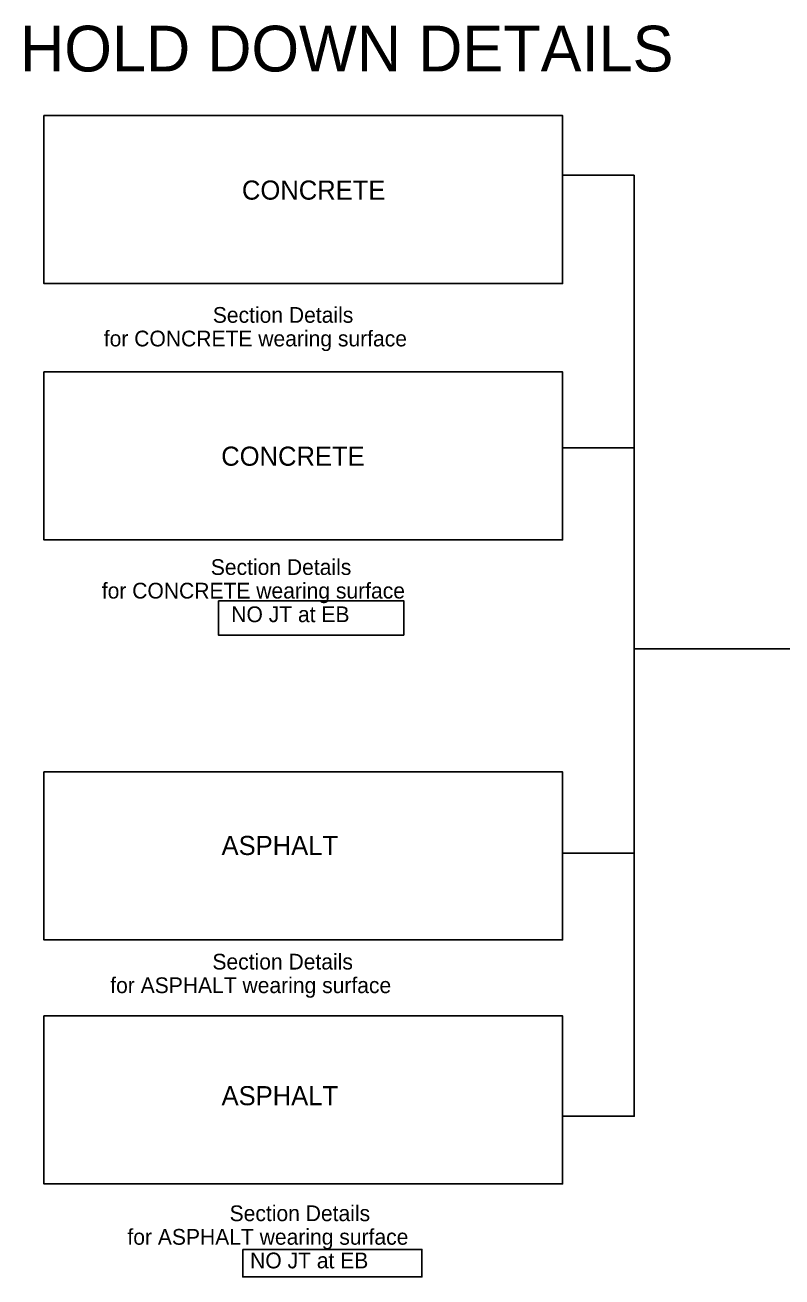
# Model space of a CAD drawing. Extents: x -408 to -23, y -15 to 117.
# Drawn here: x -408.4 to -368.8, y -9.2 to 56.3 of the extents above; entities that cross this region are included whole.
import ezdxf

# ---------------------------------------------------------------- set-up
doc = ezdxf.new("R2010")
doc.units = 0
doc.layers.add('Text', color=7, linetype='Continuous')
doc.layers.add('User Information Notes', color=7, linetype='Continuous')

msp = doc.modelspace()

# ---------------------------------------------------------------- linework, layer by layer
at = {"layer": 'User Information Notes'}
for p, q in [((-376.566, 48.496), (-380.316, 48.496)), ((-376.566, 34.22), (-380.316, 34.22)), ((-366.586, 23.703), (-376.566, 23.703)), ((-376.566, 13.007), (-380.316, 13.007))]:
    msp.add_line(p, q, dxfattribs=at)
for points in [[(-407.439, 51.61), (-380.316, 51.61), (-380.316, 42.816), (-407.439, 42.816)], [(-407.439, 38.194), (-380.316, 38.194), (-380.316, 29.4), (-407.439, 29.4)], [(-398.315, 26.222), (-388.62, 26.222), (-388.62, 24.424), (-398.315, 24.424)], [(-407.439, 17.26), (-380.316, 17.26), (-380.316, 8.466), (-407.439, 8.466)], [(-407.439, 4.495), (-380.316, 4.495), (-380.316, -4.299), (-407.439, -4.299)], [(-397.038, -7.733), (-387.667, -7.733), (-387.667, -9.171), (-397.038, -9.171)]]:
    msp.add_lwpolyline(points, close=True, dxfattribs=at)
msp.add_lwpolyline([(-376.566, 48.496), (-376.566, -0.76), (-380.316, -0.76)], dxfattribs=at)

# ---------------------------------------------------------------- texts
at = {"layer": 'Text'}
for s, height, p in [('HOLD DOWN DETAILS', 2.3952, (-408.686, 53.918)), ('Section Details ', 0.82373, (-398.606, 40.766)), ('for CONCRETE wearing surface ', 0.82373, (-404.306, 39.53)), ('Section Details ', 0.82373, (-398.71, 27.57)), ('for CONCRETE wearing surface ', 0.82373, (-404.411, 26.335)), ('NO JT at EB', 0.82373, (-397.64, 25.099)), ('Section Details ', 0.82373, (-398.626, 6.919)), ('for ASPHALT wearing surface ', 0.82373, (-403.97, 5.684)), ('Section Details ', 0.82373, (-397.727, -6.25)), ('for ASPHALT wearing surface ', 0.82373, (-403.071, -7.485)), ('NO JT at EB', 0.82373, (-396.656, -8.721))]:
    msp.add_text(s, height=height, dxfattribs=at).set_placement(p)
at = {"layer": 'User Information Notes'}
for s, p in [('CONCRETE', (-397.082, 47.211)), ('CONCRETE', (-398.165, 33.285)), ('ASPHALT', (-398.148, 12.911)), ('ASPHALT', (-398.148, -0.184))]:
    msp.add_text(s, height=1, dxfattribs=at).set_placement(p)

doc.saveas('drawing.dxf')
